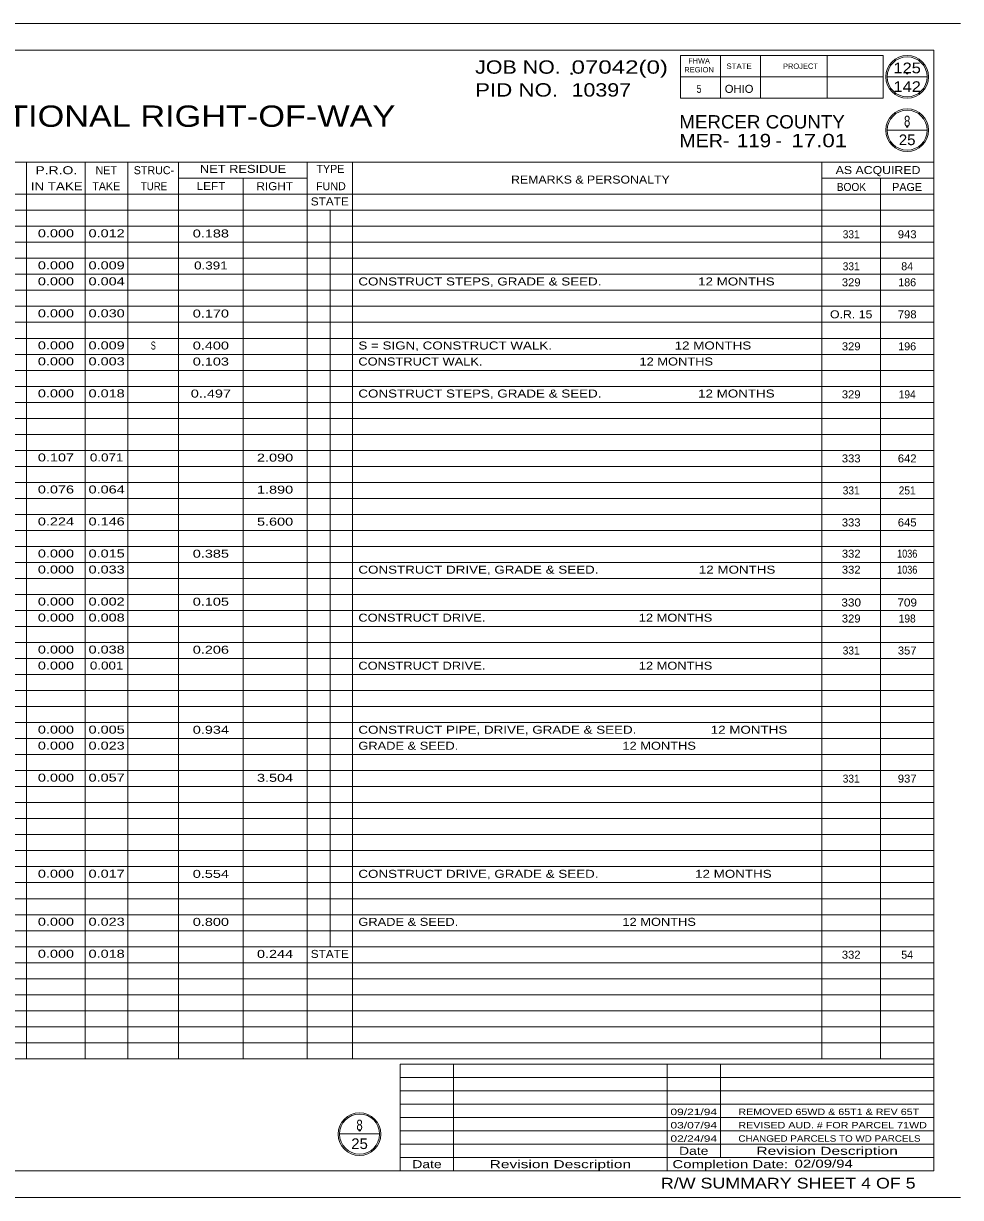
# Model space of a CAD drawing. Extents: x -1 to 34.5, y 0 to 22.
# Drawn here: x 16.94 to 34.5, y 0 to 22 of the extents above; entities that cross this region are included whole.
import ezdxf
from ezdxf.enums import TextEntityAlignment as Align

# ---------------------------------------------------------------- set-up
doc = ezdxf.new("R2010")
doc.units = 0
doc.header["$LTSCALE"] = 0.06
doc.header["$PDMODE"] = 32
doc.header["$PDSIZE"] = 0.03
doc.layers.add('1', color=7, linetype='Continuous', lineweight=13)
doc.layers.add('60', color=7, linetype='Continuous', lineweight=13)
doc.layers.add('16', color=7, linetype='Continuous')

msp = doc.modelspace()

# ---------------------------------------------------------------- linework, layer by layer
at = {"layer": '1'}
for p, q in [((22.68258, 18.50308), (22.68258, 4.7)), ((22.68258, 4.99442), (23.6175, 4.99442))]:
    msp.add_line(p, q, dxfattribs=at)
for p in [(27.21, 21.05892), (33.5, 21.06692), (33.5, 20.07), (23.2365, 1.25842)]:
    msp.add_point(p, dxfattribs=at)
at = {"layer": '60'}
for p, q in [((-1, 22), (34.5, 22)), ((0.5, 21.5), (34, 21.5)), ((30, 21.4), (30, 20.6)), ((30.75, 21.4), (30.75, 20.6)), ((32.002, 21.4), (32.002, 20.6)), ((29.25, 21), (33.05, 21)), ((33.125, 21), (33.875, 21)), ((33.125, 20.00258), (33.875, 20.00258)), ((0.5, 19.4), (34, 19.4)), ((16.99617, 2.6), (16.99617, 19.4)), ((18.09617, 2.6), (18.09617, 19.4)), ((18.89617, 2.6), (18.89617, 19.4)), ((19.84617, 2.6), (19.84617, 19.4)), ((22.253, 2.6), (22.253, 19.4)), ((23.103, 2.6), (23.103, 19.4)), ((31.90092, 2.6), (31.90092, 19.4)), ((19.853, 19.1), (22.253, 19.1)), ((21.053, 2.6), (21.053, 19.1)), ((31.90092, 19.1), (34, 19.1)), ((33.00092, 2.6), (33.00092, 19.1)), ((0.5, 18.8), (34, 18.8)), ((0.5, 18.5), (34, 18.5)), ((0.5, 18.2), (34, 18.2)), ((0.5, 17.9), (34, 17.9)), ((0.5, 17.6), (34, 17.6)), ((0.5, 17.3), (34, 17.3)), ((0.5, 17), (34, 17)), ((0.5, 16.7), (34, 16.7)), ((0.5, 16.4), (34, 16.4)), ((0.5, 16.1), (34, 16.1)), ((0.5, 15.8), (34, 15.8)), ((0.5, 15.5), (34, 15.5)), ((0.5, 15.2), (34, 15.2)), ((0.5, 14.9), (34, 14.9)), ((0.5, 14.6), (34, 14.6)), ((0.5, 14.3), (34, 14.3)), ((0.5, 14), (34, 14)), ((0.5, 13.7), (34, 13.7)), ((0.5, 13.4), (34, 13.4)), ((0.5, 13.1), (34, 13.1)), ((0.5, 12.8), (34, 12.8)), ((0.5, 12.5), (34, 12.5)), ((0.5, 12.2), (34, 12.2)), ((0.5, 11.9), (34, 11.9)), ((0.5, 11.6), (34, 11.6)), ((0.5, 11.3), (34, 11.3)), ((0.5, 11), (34, 11)), ((0.5, 10.7), (34, 10.7)), ((0.5, 10.4), (34, 10.4)), ((0.5, 10.1), (34, 10.1)), ((0.5, 9.8), (34, 9.8)), ((0.5, 9.5), (34, 9.5)), ((0.5, 9.2), (34, 9.2)), ((0.5, 8.9), (34, 8.9)), ((0.5, 8.6), (34, 8.6)), ((0.5, 8.3), (34, 8.3)), ((0.5, 8), (34, 8)), ((0.5, 7.7), (34, 7.7)), ((0.5, 7.4), (34, 7.4)), ((0.5, 7.1), (34, 7.1)), ((0.5, 6.8), (34, 6.8)), ((0.5, 6.5), (34, 6.5)), ((0.5, 6.2), (34, 6.2)), ((0.5, 5.9), (34, 5.9)), ((0.5, 5.6), (34, 5.6)), ((0.5, 5.3), (34, 5.3)), ((0.5, 5), (34, 5)), ((0.5, 4.7), (34, 4.7)), ((0.5, 4.4), (34, 4.4)), ((0.5, 4.1), (34, 4.1)), ((0.5, 3.8), (34, 3.8)), ((0.5, 3.5), (34, 3.5)), ((0.5, 3.2), (34, 3.2)), ((0.5, 2.9), (34, 2.9)), ((0.5, 2.6), (34, 2.6)), ((34, 2.5), (24, 2.5)), ((24, 2.5), (24, 0.5)), ((25, 2.5), (25, 0.5)), ((29, 2.5), (29, 0.5)), ((30, 2.5), (30, 0.75)), ((34, 2.25), (24, 2.25)), ((34, 2), (24, 2)), ((34, 1.75), (24, 1.75)), ((34, 1.5), (24, 1.5)), ((22.8615, 1.191), (23.6115, 1.191)), ((34, 1.25), (24, 1.25)), ((34, 1), (24, 1)), ((34, 0.75), (24, 0.75)), ((-1, 0), (34.5, 0))]:
    msp.add_line(p, q, dxfattribs=at)
msp.add_lwpolyline([(34, 21.5), (34, 0.5), (0.5, 0.5)], dxfattribs=at)
msp.add_lwpolyline([(29.25, 20.6), (33.05, 20.6), (33.05, 21.4), (29.25, 21.4)], close=True, dxfattribs=at)
for centre, radius in [((33.5, 21), 0.4), ((33.5, 21), 0.375), ((33.5, 20), 0.4), ((33.5, 20), 0.375), ((23.23653, 1.18838), 0.4), ((23.23653, 1.18838), 0.375)]:
    msp.add_circle(centre, radius, dxfattribs=at)

# ---------------------------------------------------------------- texts
at = {"layer": '1'}
for s, height, width, p in [('MERCER COUNTY', 0.25, 1.05, (29.22958, 20.03208)), ('MER-', 0.25, 1.1, (29.22958, 19.68208)), ('17.01', 0.25, 1.25, (31.32958, 19.68208)), ('-', 0.25, 1.1, (31.02958, 19.68208)), ('CONSTRUCT STEPS, GRADE & SEED.                          12 MONTHS', 0.15, 1.25, (23.21425, 17.09067)), ('S = SIGN, CONSTRUCT WALK.                                 12 MONTHS', 0.15, 1.25, (23.21425, 15.89067)), ('CONSTRUCT WALK.                                            12 MONTHS', 0.15, 1.2, (23.21425, 15.59067)), ('CONSTRUCT STEPS, GRADE & SEED.                          12 MONTHS', 0.15, 1.25, (23.21425, 14.99067)), ('CONSTRUCT DRIVE, GRADE & SEED.                           12 MONTHS', 0.15, 1.25, (23.21425, 11.69067)), ('CONSTRUCT DRIVE.                                           12 MONTHS', 0.15, 1.2, (23.21425, 10.79067)), ('CONSTRUCT DRIVE.                                           12 MONTHS', 0.15, 1.2, (23.21425, 9.89067)), ('CONSTRUCT PIPE, DRIVE, GRADE & SEED.                    12 MONTHS', 0.15, 1.25, (23.21425, 8.69067)), ('GRADE & SEED.                                              12 MONTHS', 0.15, 1.2, (23.21425, 8.39067)), ('CONSTRUCT DRIVE, GRADE & SEED.                          12 MONTHS', 0.15, 1.25, (23.21425, 5.99067)), ('GRADE & SEED.                                              12 MONTHS', 0.15, 1.2, (23.21425, 5.09067)), ('09/21/94', 0.12, 1.4, (29.06317, 1.54383)), ('REMOVED 65WD & 65T1 & REV 65T', 0.12, 1.25, (30.33625, 1.546)), ('03/07/94', 0.12, 1.4, (29.06317, 1.29383)), ('REVISED AUD. # FOR PARCEL 71WD', 0.12, 1.25, (30.33625, 1.296)), ('02/24/94', 0.12, 1.4, (29.06317, 1.04383)), ('CHANGED PARCELS TO WD PARCELS', 0.12, 1.15, (30.33625, 1.046)), ('02/09/94', 0.15, 1.4, (31.38917, 0.55942))]:
    msp.add_text(s, height=height, dxfattribs=dict(at, width=width)).set_placement(p)
for s, height, width, p in [('119', 0.25, 1.15, (30.62958, 19.68208)), ('STATE', 0.15, 1.1, (22.678, 18.59)), ('0.000', 0.15, 1.35, (17.54621, 17.99317)), ('0.012', 0.15, 1.35, (18.49612, 17.99317)), ('0.188', 0.15, 1.35, (20.44963, 17.99)), ('331', 0.15, 0.95, (32.45092, 17.975)), ('943', 0.15, 1.05, (33.50046, 17.975)), ('0.000', 0.15, 1.35, (17.54621, 17.39317)), ('0.009', 0.15, 1.35, (18.49612, 17.39317)), ('0.391', 0.15, 1.25, (20.44967, 17.39)), ('331', 0.15, 0.95, (32.45092, 17.375)), ('0.000', 0.15, 1.35, (17.54621, 17.09317)), ('0.004', 0.15, 1.35, (18.49612, 17.09317)), ('329', 0.15, 1.05, (32.45096, 17.075)), ('0.000', 0.15, 1.35, (17.54621, 16.49317)), ('0.030', 0.15, 1.35, (18.49621, 16.49317)), ('0.170', 0.15, 1.35, (20.44971, 16.49)), ('O.R. 15', 0.15, 1.15, (32.45087, 16.475)), ('798', 0.15, 1.05, (33.50046, 16.475)), ('0.000', 0.15, 1.35, (17.54621, 15.89317)), ('0.009', 0.15, 1.35, (18.49612, 15.89317)), ('S', 0.15, 0.7, (19.37112, 15.89)), ('0.400', 0.15, 1.35, (20.44971, 15.89)), ('329', 0.15, 1.05, (32.45096, 15.875)), ('0.000', 0.15, 1.35, (17.54621, 15.59317)), ('0.003', 0.15, 1.35, (18.49612, 15.59317)), ('0.103', 0.15, 1.35, (20.44963, 15.59)), ('0.000', 0.15, 1.35, (17.54621, 14.99317)), ('0.018', 0.15, 1.35, (18.49612, 14.99317)), ('0..497', 0.15, 1.35, (20.44971, 14.99)), ('329', 0.15, 1.05, (32.45096, 14.975)), ('194', 0.15, 0.95, (33.5005, 14.975)), ('0.107', 0.15, 1.35, (17.54612, 13.79317)), ('0.071', 0.15, 1.25, (18.49617, 13.79317)), ('2.090', 0.15, 1.35, (21.65304, 13.79)), ('333', 0.15, 1.05, (32.45087, 13.775)), ('642', 0.15, 1.05, (33.5005, 13.775)), ('0.076', 0.15, 1.35, (17.54621, 13.19317)), ('0.064', 0.15, 1.35, (18.49612, 13.19317)), ('1.890', 0.15, 1.35, (21.65304, 13.19)), ('331', 0.15, 0.95, (32.45092, 13.175)), ('251', 0.15, 0.95, (33.5005, 13.175)), ('0.224', 0.15, 1.35, (17.54612, 12.59317)), ('0.146', 0.15, 1.35, (18.49621, 12.59317)), ('5.600', 0.15, 1.35, (21.65304, 12.59)), ('333', 0.15, 1.05, (32.45087, 12.575)), ('645', 0.15, 1.05, (33.5005, 12.575)), ('0.000', 0.15, 1.35, (17.54621, 11.99317)), ('0.015', 0.15, 1.35, (18.49612, 11.99317)), ('0.385', 0.15, 1.35, (20.44963, 11.99)), ('332', 0.15, 1.05, (32.45087, 11.99)), ('1036', 0.15, 0.85, (33.50092, 11.99)), ('0.000', 0.15, 1.35, (17.54621, 11.69317)), ('0.033', 0.15, 1.35, (18.49612, 11.69317)), ('332', 0.15, 1.05, (32.45087, 11.69)), ('1036', 0.15, 0.85, (33.50092, 11.69)), ('0.000', 0.15, 1.35, (17.54621, 11.09317)), ('0.002', 0.15, 1.35, (18.49612, 11.09317)), ('0.105', 0.15, 1.35, (20.44963, 11.09)), ('330', 0.15, 1.1, (32.45087, 11.075)), ('709', 0.15, 1.1, (33.50046, 11.075)), ('0.000', 0.15, 1.35, (17.54621, 10.79317)), ('0.008', 0.15, 1.35, (18.49612, 10.79317)), ('329', 0.15, 1.05, (32.45096, 10.775)), ('198', 0.15, 0.95, (33.5005, 10.775)), ('0.000', 0.15, 1.35, (17.54621, 10.19317)), ('0.038', 0.15, 1.35, (18.49612, 10.19317)), ('0.206', 0.15, 1.35, (20.44971, 10.19)), ('331', 0.15, 0.95, (32.45092, 10.175)), ('357', 0.15, 1.05, (33.50046, 10.175)), ('0.000', 0.15, 1.35, (17.54621, 9.89317)), ('0.001', 0.15, 1.25, (18.49617, 9.89317)), ('0.000', 0.15, 1.35, (17.54621, 8.69317)), ('0.005', 0.15, 1.35, (18.49612, 8.69317)), ('0.934', 0.15, 1.35, (20.44963, 8.69)), ('0.000', 0.15, 1.35, (17.54621, 8.39317)), ('0.023', 0.15, 1.35, (18.49612, 8.39317)), ('0.000', 0.15, 1.35, (17.54621, 7.79317)), ('0.057', 0.15, 1.35, (18.49612, 7.79317)), ('3.504', 0.15, 1.35, (21.65296, 7.79)), ('331', 0.15, 0.95, (32.45092, 7.775)), ('937', 0.15, 1.05, (33.50046, 7.775)), ('0.000', 0.15, 1.35, (17.54621, 5.99317)), ('0.017', 0.15, 1.35, (18.49612, 5.99317)), ('0.554', 0.15, 1.35, (20.44963, 5.99)), ('0.000', 0.15, 1.35, (17.54621, 5.09317)), ('0.023', 0.15, 1.35, (18.49612, 5.09317)), ('0.800', 0.15, 1.35, (20.44971, 5.09)), ('0.000', 0.15, 1.35, (17.54621, 4.49317)), ('0.018', 0.15, 1.35, (18.49612, 4.49317)), ('0.244', 0.15, 1.35, (21.65296, 4.49)), ('STATE', 0.15, 1.1, (22.678, 4.49)), ('332', 0.15, 1.05, (32.45087, 4.475))]:
    msp.add_text(s, height=height, dxfattribs=dict(at, width=width)).set_placement(p, align=Align.CENTER)
for s, p in [('84', (33.50046, 17.375)), ('186', (33.50054, 17.075)), ('196', (33.50054, 15.875)), ('54', (33.50046, 4.475))]:
    msp.add_text(s, height=0.15, dxfattribs=at).set_placement(p, align=Align.CENTER)
at = {"layer": '16'}
for s, width, p in [('07042(0)', 1.35, (27.21, 21.05892)), ('10397', 1.2, (27.21, 20.63033))]:
    msp.add_text(s, height=0.25, dxfattribs=dict(at, width=width)).set_placement(p)
for s, width, p in [('125', 1.15, (33.5, 21.06692)), ('142', 1.15, (33.5, 20.71692)), ('8', 0.8, (33.5, 20.07)), ('25', 1.05, (33.49996, 19.72)), ('8', 0.8, (23.2365, 1.25842)), ('25', 1.05, (23.23646, 0.90842))]:
    msp.add_text(s, height=0.2, dxfattribs=dict(at, width=width)).set_placement(p, align=Align.CENTER)
at = {"layer": '60'}
for s, height, width, p in [('FHWA', 0.1, 0.95, (29.60004, 21.25)), ('REGION', 0.1, 1.05, (29.6, 21.08333)), ('STATE', 0.1, 1.1, (30.35, 21.15)), ('PROJECT', 0.1, 1.05, (31.50004, 21.15)), ('5', 0.15, 0.8, (29.6, 20.7)), ('OHIO', 0.15, 1.05, (30.35004, 20.7)), ('SUMMARY OF ADDITIONAL RIGHT-OF-WAY', 0.4, 1.2, (17.2385, 20.06342)), ('P.R.O.', 0.15, 1.3, (17.55308, 19.175)), ('NET RESIDUE', 0.15, 1.2, (21.05304, 19.2)), ('REMARKS & PERSONALTY', 0.15, 1.15, (27.56296, 19)), ('AS ACQUIRED', 0.15, 1.15, (32.95442, 19.17858)), ('IN TAKE', 0.15, 1.25, (17.56058, 18.875)), ('LEFT', 0.15, 1.1, (20.45296, 18.87867)), ('RIGHT', 0.15, 1.1, (21.64696, 18.87642)), ('BOOK', 0.15, 0.95, (32.45529, 18.86167)), ('Date', 0.15, 1.3, (29.5, 0.8)), ('Revision Description', 0.15, 1.45, (32, 0.8)), ('Date', 0.15, 1.3, (24.5, 0.55)), ('Revision Description', 0.15, 1.45, (27, 0.55))]:
    msp.add_text(s, height=height, dxfattribs=dict(at, width=width)).set_placement(p, align=Align.CENTER)
for s, height, width, p in [('JOB NO.', 0.25, 1.2, (25.40233, 21.05892)), ('PID NO.', 0.25, 1.25, (25.40233, 20.63033)), ('TURE', 0.15, 0.9, (19.13825, 18.87483)), ('Completion Date:', 0.15, 1.4, (29.1, 0.55))]:
    msp.add_text(s, height=height, dxfattribs=dict(at, width=width)).set_placement(p)
for s, p in [('NET', (18.48912, 19.175)), ('STRUC-', (19.38237, 19.17558)), ('TYPE', (22.691, 19.2)), ('TAKE', (18.48908, 18.875)), ('FUND', (22.69962, 18.87642)), ('PAGE', (33.49883, 18.86167))]:
    msp.add_text(s, height=0.15, dxfattribs=at).set_placement(p, align=Align.CENTER)
at = {"layer": '60', "width": 1.25}
msp.add_text('R/W SUMMARY SHEET 4 OF 5', height=0.2, dxfattribs=at).set_placement((33.65833, 0.16892), align=Align.RIGHT)

doc.saveas('drawing.dxf')
